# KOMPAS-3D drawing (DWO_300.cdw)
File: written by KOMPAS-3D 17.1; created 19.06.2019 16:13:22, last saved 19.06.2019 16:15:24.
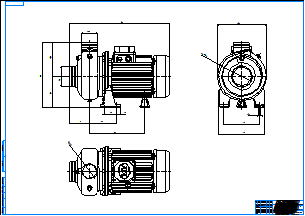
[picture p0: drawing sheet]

Sheet 1: A0, landscape

Title block, sheet 1: name: DWO_300; material: Внимание! Данный продукт является объектом авторского права ООО «Торговый Дом АДЛ». / Запрещается изменение, копирование, распространение / (в том числе путем копирования на другие сайты и ресурсы в Интернете) / или любое иное использование информации и объектов без предварительного / согласия правообладателя (ООО «Торговый Дом АДЛ»).; scale: 1:1; sheets: 1; organisation: ООО "Торговый дом АДЛ"; sheet format: A0; stored path: \\adlc.lan\data\АДЛ_ПКД\3D-модели\Поставщики\Насосное оборудование EBARA\DWO\KOMPAS 2D\DWO_300.cdw

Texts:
  user
  CONTINUOUS_RGB_0_0_0_THICK_0.18
  POLYLINE_STYLE_0.18_RGB_0_0_0
Dimensions and other numbers on the sheet: 50; 15; 107; 78; 390; 215.5; 120; 133; 253; 80; 62.5; 193; 140; 180; 9; 72; 57; 1:1; 1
